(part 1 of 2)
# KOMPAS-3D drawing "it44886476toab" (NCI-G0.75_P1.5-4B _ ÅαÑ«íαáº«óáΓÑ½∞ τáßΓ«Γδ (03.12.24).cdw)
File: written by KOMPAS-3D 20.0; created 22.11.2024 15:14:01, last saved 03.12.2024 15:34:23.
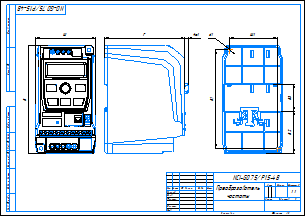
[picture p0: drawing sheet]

Sheet 1: A3, landscape

Document properties: Полное имя файла: P:\INSTART\Технический отдел\ОР\Прочие задачи\КД на номенклатурный ряд\КД на типоразмеры ПЧ\NCI\NCI-G0.75_P1.5-4B\NCI-G0.75_P1.5-4B _ Преобразователь частоты (03.12.24).cdw; Автор: admin

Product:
- Part/product: it44886476toab
    Масса: 2.32322
  - Body: Тело 2
      Масса: 0.00113358
  - Body: Тело 3
      Масса: 0.00113358
  - Body: Тело 4
      Масса: 0.000355433
  - Body: Тело 6
      Масса: 0.000355433
  - Body: Тело 7
      Масса: 0.000703761
  - Body: Тело 8
      Масса: 0.000703761
  - Body: Тело 10
      Масса: 0.0160396
  - Body: Тело 11
      Масса: 0.000703761
  - Body: Тело 13
      Масса: 0.000703761
  - Body: Тело 14
      Масса: 0.000703761
  - Body: Тело 18
      Масса: 0.0117014
  - Body: Тело 20
      Масса: 0.120334
  - Body: Тело 21
      Масса: 0.0864411
  - Body: Тело 22
      Масса: 0.0636504
  - Body: Тело 25
      Масса: 0.00135688
  - Body: Тело 26
      Масса: 0.00135688
  - Body: Тело 27
      Масса: 0.00135688
  - Body: Тело 30
      Масса: 0.000935996
  - Body: Тело 34
      Масса: 0.00831628
  - Body: Тело 36
      Масса: 0.0668131
  - Body: Тело 37
      Масса: 0.0343584
  - Body: Тело 39
      Масса: 0.0119524
  - Body: Тело 40
      Масса: 0.0119524
  - Body: Тело 42
      Масса: 0.0119524
  - Body: Тело 43
      Масса: 0.0119524
  - Body: Тело 46
      Масса: 0.0119034
  - Body: Тело 47
      Масса: 0.551587
  - Body: Тело 51
      Масса: 1.32696e-05
  - Body: Тело 54
      Масса: 1.32696e-05
  - Body: Тело 55
      Масса: 1.32696e-05
  - Body: Тело 56
      Масса: 1.32696e-05
  - Body: Тело 58
      Масса: 1.32696e-05
  - Body: Тело 61
      Масса: 1.32696e-05
  - Body: Тело 57
      Масса: 1.32696e-05
  - Body: Тело 63
      Масса: 1.65581e-05
  - Body: Тело 66
      Масса: 1.65581e-05
  - Body: Тело 67
      Масса: 1.65581e-05
  - Body: Тело 68
      Масса: 1.65581e-05
  - Body: Тело 69
      Масса: 1.65581e-05
  - Body: Тело 73
      Масса: 1.65581e-05
  - Body: Тело 48
      Масса: 0.00853877
  - Body: Тело 74
      Масса: 1.65581e-05
  - Body: Тело 78
      Масса: 1.65581e-05
  - Body: Тело 79
      Масса: 1.32696e-05
  - Body: Тело 80
      Масса: 1.32696e-05
  - Body: Тело 82
      Масса: 1.32696e-05
  - Body: Тело 83
      Масса: 1.32696e-05
  - Body: Тело 84
      Масса: 1.32696e-05
  - Body: Тело 87
      Масса: 0.000966482
  - Body: Тело 88
      Масса: 0.000873873
  - Body: Тело 15
      Масса: 0.000703761
  - Body: Тело 91
      Масса: 0.0246688
  - Body: Тело 92
      Масса: 3.83377e-05
  - Body: Тело 94
      Масса: 0.00554276
  - Body: Тело 96
      Масса: 0.00181049
  - Body: Тело 101
      Масса: 1.32696e-05
  - Body: Тело 90
      Масса: 0.000966482
  - Body: Тело 102
      Масса: 1.32696e-05
  - Body: Тело 104
      Масса: 1.32696e-05
  - Body: Тело 107
      Масса: 1.32696e-05
  - Body: Тело 108
      Масса: 1.32696e-05
  - Body: Тело 111
      Масса: 0.000194606
  - Body: Тело 115
      Масса: 0.000413213
  - Body: Тело 123
      Масса: 1.65581e-05
  - Body: Тело 127
      Масса: 1.32696e-05
  - Body: Тело 128
      Масса: 1.32696e-05
  - Body: Тело 129
      Масса: 1.32696e-05
  - Body: Тело 112
      Масса: 0.000413213
  - Body: Тело 130
      Масса: 1.32696e-05
  - Body: Тело 16
      Масса: 0.000703761
  - Body: Тело 131
      Масса: 1.32696e-05
  - Body: Тело 132
      Масса: 1.32696e-05
  - Body: Тело 133
      Масса: 1.32696e-05
  - Body: Тело 38
      Масса: 0.00631989
  - Body: Тело 135
      Масса: 1.32696e-05
  - Body: Тело 136
      Масса: 1.32696e-05
  - Body: Тело 142
      Масса: 0.000213463
  - Body: Тело 144
      Масса: 1.32696e-05
  - Body: Тело 62
      Масса: 1.32696e-05
  - Body: Тело 24
      Масса: 0.0110484
  - Body: Тело 147
      Масса: 1.32696e-05
  - Body: Тело 148
      Масса: 1.32696e-05
  - Body: Тело 154
      Масса: 1.32696e-05
  - Body: Тело 156
      Масса: 1.32696e-05
  - Body: Тело 158
      Масса: 1.32696e-05
  - Body: Тело 116
      Масса: 0.000413213
  - Body: Тело 159
      Масса: 1.32696e-05
  - Body: Тело 165
      Масса: 1.65581e-05
  - Body: Тело 166
      Масса: 1.32696e-05
  - Body: Тело 140
      Масса: 0.000213463
  - Body: Тело 169
      Масса: 1.32696e-05
  - Body: Тело 171
      Масса: 1.32696e-05
  - Body: Тело 153
      Масса: 1.32696e-05
  - Body: Тело 172
      Масса: 1.65581e-05
  - Body: Тело 173
      Масса: 1.32696e-05
  - Body: Тело 137
      Масса: 1.32696e-05
  - Body: Тело 45
      Масса: 0.0267013
  - Body: Тело 175
      Масса: 1.32696e-05
  - Body: Тело 177
      Масса: 1.32696e-05
  - Body: Тело 50
      Масса: 0.00101975
  - Body: Тело 44
      Масса: 0.0119524
  - Body: Тело 178
      Масса: 1.32696e-05
  - Body: Тело 179
      Масса: 1.32696e-05
  - Body: Тело 181
      Масса: 1.32696e-05
  - Body: Тело 182
      Масса: 1.32696e-05
  - Body: Тело 183
      Масса: 1.32696e-05
  - Body: Тело 188
      Масса: 1.32696e-05
  - Body: Тело 189
      Масса: 1.32696e-05
  - Body: Тело 192
      Масса: 1.32696e-05
  - Body: Тело 195
      Масса: 1.32696e-05
  - Body: Тело 197
      Масса: 1.32696e-05
  - Body: Тело 198
      Масса: 1.32696e-05
  - Body: Тело 199
      Масса: 1.32696e-05
  - Body: Тело 29
      Масса: 0.00135688
  - Body: Тело 201
      Масса: 1.32696e-05
  - Body: Тело 202
      Масса: 1.32696e-05
  - Body: Тело 205
      Масса: 1.32696e-05
  - Body: Тело 208
      Масса: 1.7366e-05
  - Body: Тело 209
      Масса: 1.32696e-05
  - Body: Тело 211
      Масса: 1.32696e-05
  - Body: Тело 212
      Масса: 1.32696e-05
  - Body: Тело 214
      Масса: 1.32696e-05
  - Body: Тело 9
      Масса: 0.000703761
  - Body: Тело 215
      Масса: 1.65581e-05
  - Body: Тело 217
      Масса: 1.32696e-05
  - Body: Тело 218
      Масса: 1.32696e-05
  - Body: Тело 219
      Масса: 1.32696e-05
  - Body: Тело 220
      Масса: 1.32696e-05
  - Body: Тело 221
      Масса: 1.65581e-05
  - Body: Тело 223
      Масса: 1.32696e-05
  - Body: Тело 162
      Масса: 1.65581e-05
  - Body: Тело 224
      Масса: 1.32696e-05
  - Body: Тело 228
      Масса: 1.32696e-05
  - Body: Тело 184
      Масса: 1.32696e-05
  - Body: Тело 230
      Масса: 1.32696e-05
  - Body: Тело 231
      Масса: 0.00398049
  - Body: Тело 232
      Масса: 5.48304e-05
  - Body: Тело 233
      Масса: 1.7366e-05
  - Body: Тело 1
      Масса: 0.00113358
  - Body: Тело 237
      Масса: 1.7366e-05
  - Body: Тело 141
      Масса: 0.000213463
  - Body: Тело 241
      Масса: 0.000424983
  - Body: Тело 65
      Масса: 1.65581e-05
  - Body: Тело 242
      Масса: 1.65581e-05
  - Body: Тело 243
      Масса: 1.65581e-05
  - Body: Тело 245
      Масса: 1.65581e-05
  - Body: Тело 234
      Масса: 1.7366e-05
  - Body: Тело 114
      Масса: 0.000413213
  - Body: Тело 19
      Масса: 0.0117014
  - Body: Тело 248
      Масса: 1.7366e-05
  - Body: Тело 249
      Масса: 1.7366e-05
  - Body: Тело 250
      Масса: 1.7366e-05
  - Body: Тело 254
      Масса: 1.32696e-05
  - Body: Тело 255
      Масса: 1.7366e-05
  - Body: Тело 119
      Масса: 0.000413213
  - Body: Тело 256
      Масса: 1.7366e-05
  - Body: Тело 167
      Масса: 1.32696e-05
  - Body: Тело 260
      Масса: 1.7366e-05
  - Body: Тело 261
      Масса: 3.83377e-05
  - Body: Тело 170
      Масса: 1.32696e-05
  - Body: Тело 463
      Масса: 0.000404362
  - Body: Тело 226
      Масса: 0.000413213
  - Body: Тело 464
      Масса: 0.00829425
  - Body: Тело 268
      Масса: 5.48304e-05
  - Body: Тело 467
      Масса: 0.00436982
  - Body: Тело 475
      Масса: 1.51773e-05
  - Body: Тело 451
      Масса: 6.34685e-05
  - Body: Тело 478
      Масса: 1.51773e-05
  - Body: Тело 465
      Масса: 0.00829114
  - Body: Тело 383
      Масса: 0.000340816
  - Body: Тело 125
      Масса: 1.65581e-05
  - Body: Тело 643
      Масса: 0.000158536
  - Body: Тело 514
      Масса: 1.51773e-05
  - Body: Тело 483
      Масса: 1.51773e-05
  - Body: Тело 486
      Масса: 0.000158536
  - Body: Тело 581
      Масса: 1.65581e-05
  - Body: Тело 490
      Масса: 1.51773e-05
  - Body: Тело 491
      Масса: 1.65581e-05
  - Body: Тело 433
      Масса: 0.000118347
  - Body: Тело 496
      Масса: 1.51773e-05
  - Body: Тело 437
      Масса: 0.00113358
  - Body: Тело 535
      Масса: 1.52051e-05
  - Body: Тело 498
      Масса: 1.51773e-05
  - Body: Тело 60
      Масса: 1.32696e-05
  - Body: Тело 369
      Масса: 1.32696e-05
  - Body: Тело 501
      Масса: 1.51773e-05
  - Body: Тело 503
      Масса: 1.51773e-05
  - Body: Тело 447
      Масса: 0.000307437
  - Body: Тело 187
      Масса: 1.32696e-05
  - Body: Тело 12
      Масса: 0.000703761
  - Body: Тело 507
      Масса: 1.51773e-05
  - Body: Тело 174
      Масса: 1.65581e-05
  - Body: Тело 587
      Масса: 1.32696e-05
  - Body: Тело 155
      Масса: 1.32696e-05
  - Body: Тело 512
      Масса: 1.51773e-05
  - Body: Тело 515
      Масса: 0.00507372
  - Body: Тело 510
      Масса: 1.51773e-05
  - Body: Тело 487
      Масса: 1.65581e-05
  - Body: Тело 432
      Масса: 0.000118347
  - Body: Тело 524
      Масса: 1.65581e-05
  - Body: Тело 637
      Масса: 1.51773e-05
  - Body: Тело 519
      Масса: 1.7366e-05
  - Body: Тело 427
      Масса: 1.32696e-05
  - Body: Тело 520
      Масса: 5.48304e-05
  - Body: Тело 326
      Масса: 1.32696e-05
  - Body: Тело 509
      Масса: 1.51773e-05
  - Body: Тело 571
      Масса: 0.00166679
  - Body: Тело 521
      Масса: 1.32696e-05
  - Body: Тело 522
      Масса: 1.65581e-05
  - Body: Тело 49
      Масса: 0.00944
  - Body: Тело 319
      Масса: 1.32696e-05
  - Body: Тело 458
      Масса: 1.51773e-05
  - Body: Тело 523
      Масса: 0.000255388
  - Body: Тело 191
      Масса: 1.32696e-05
  - Body: Тело 590
      Масса: 1.32696e-05
  - Body: Тело 599
      Масса: 7.12116e-06
  - Body: Тело 528
      Масса: 0.000141095
  - Body: Тело 64
      Масса: 1.65581e-05
  - Body: Тело 468
      Масса: 0.0253857
  - Body: Тело 216
      Масса: 0.000280294
  - Body: Тело 443
      Масса: 0.00113358
  - Body: Тело 239
      Масса: 5.48304e-05
  - Body: Тело 200
      Масса: 1.32696e-05
  - Body: Тело 579
      Масса: 0.00017125
  - Body: Тело 529
      Масса: 5.61948e-05
  - Body: Тело 493
      Масса: 1.51773e-05
  - Body: Тело 532
      Масса: 5.61948e-05
  - Body: Тело 343
      Масса: 0.00166679
  - Body: Тело 616
      Масса: 1.63919e-05
  - Body: Тело 462
      Масса: 0.000404362
  - Body: Тело 542
      Масса: 0.000158536
  - Body: Тело 543
      Масса: 0.000158536
  - Body: Тело 615
      Масса: 1.63919e-05
  - Body: Тело 149
      Масса: 1.32696e-05
  - Body: Тело 146
      Масса: 1.32696e-05
  - Body: Тело 469
      Масса: 0.0113891
  - Body: Тело 544
      Масса: 0.000158536
  - Body: Тело 295
      Масса: 1.65581e-05
  - Body: Тело 120
      Масса: 0.000413213
  - Body: Тело 352
      Масса: 2.90876e-05
  - Body: Тело 502
      Масса: 1.51773e-05
  - Body: Тело 461
      Масса: 0.000404362
  - Body: Тело 145
      Масса: 1.32696e-05
  - Body: Тело 545
      Масса: 1.51773e-05
  - Body: Тело 506
      Масса: 1.51773e-05
  - Body: Тело 71
      Масса: 1.65581e-05
  - Body: Тело 41
      Масса: 0.0119524
  - Body: Тело 547
      Масса: 0.000255388
  - Body: Тело 614
      Масса: 1.63919e-05
  - Body: Тело 257
      Масса: 1.7366e-05
  - Body: Тело 549
      Масса: 0.000255388
  - Body: Тело 204
      Масса: 1.32696e-05
  - Body: Тело 35
      Масса: 0.262997
  - Body: Тело 421
      Масса: 1.7366e-05
  - Body: Тело 258
      Масса: 1.7366e-05
  - Body: Тело 504
      Масса: 1.51773e-05
  - Body: Тело 366
      Масса: 1.7366e-05
  - Body: Тело 592
      Масса: 7.12116e-06
  - Body: Тело 32
      Масса: 0.0135217
  - Body: Тело 550
      Масса: 0.000255388
  - Body: Тело 157
      Масса: 1.32696e-05
  - Body: Тело 126
      Масса: 0.000512664
  - Body: Тело 314
      Масса: 1.7366e-05
  - Body: Тело 247
      Масса: 1.7366e-05
  - Body: Тело 23
      Масса: 0.0243258
  - Body: Тело 595
      Масса: 1.32696e-05
  - Body: Тело 534
      Масса: 1.32696e-05
  - Body: Тело 552
      Масса: 4.06595e-05
  - Body: Тело 176
      Масса: 1.32696e-05
  - Body: Тело 553
      Масса: 4.06595e-05
  - Body: Тело 28
      Масса: 0.00135688
  - Body: Тело 330
      Масса: 1.7366e-05
  - Body: Тело 190
      Масса: 1.32696e-05
  - Body: Тело 416
      Масса: 1.7366e-05
  - Body: Тело 435
      Масса: 0.00113358
  - Body: Тело 634
      Масса: 1.51773e-05
  - Body: Тело 555
      Масса: 0.00166679
  - Body: Тело 556
      Масса: 0.00166679
  - Body: Тело 602
      Масса: 5.61948e-05
  - Body: Тело 630
      Масса: 1.51773e-05
  - Body: Тело 558
      Масса: 0.00726683
  - Body: Тело 505
      Масса: 1.51773e-05
  - Body: Тело 500
      Масса: 1.51773e-05
  - Body: Тело 72
      Масса: 1.65581e-05
  - Body: Тело 279
      Масса: 1.32696e-05
  - Body: Тело 298
      Масса: 3.64495e-05
  - Body: Тело 168
      Масса: 1.32696e-05
  - Body: Тело 495
      Масса: 1.51773e-05
  - Body: Тело 336
      Масса: 3.64028e-05
  - Body: Тело 629
      Масса: 1.51773e-05
  - Body: Тело 263
      Масса: 1.7366e-05
  - Body: Тело 610
      Масса: 0.00166679
  - Body: Тело 609
      Масса: 1.7366e-05
  - Body: Тело 596
      Масса: 1.32696e-05
  - Body: Тело 538
      Масса: 1.51773e-05
  - Body: Тело 476
      Масса: 1.51773e-05
  - Body: Тело 227
      Масса: 1.32696e-05
  - Body: Тело 382
      Масса: 5.48304e-05
  - Body: Тело 470
      Масса: 0.00329329
  - Body: Тело 341
      Масса: 0.00166679
  - Body: Тело 426
      Масса: 1.32696e-05
  - Body: Тело 513
      Масса: 1.51773e-05
  - Body: Тело 236
      Масса: 1.7366e-05
  - Body: Тело 585
      Масса: 4.06595e-05
  - Body: Тело 649
      Масса: 0.00426189
  - Body: Тело 531
      Масса: 5.61948e-05
  - Body: Тело 627
      Масса: 0.000255388
  - Body: Тело 621
      Масса: 1.32696e-05
  - Body: Тело 349
      Масса: 1.7366e-05
  - Body: Тело 580
      Масса: 1.32696e-05
  - Body: Тело 631
      Масса: 1.51773e-05
  - Body: Тело 185
      Масса: 1.32696e-05
  - Body: Тело 117
      Масса: 0.000413213
  - Body: Тело 623
      Масса: 1.32696e-05
  - Body: Тело 605
      Масса: 5.61948e-05
  - Body: Тело 400
      Масса: 1.7366e-05
  - Body: Тело 139
      Масса: 0.000194606
  - Body: Тело 492
      Масса: 1.51773e-05
  - Body: Тело 612
      Масса: 0.000158536
  - Body: Тело 403
      Масса: 1.7366e-05
  - Body: Тело 460
      Масса: 3.90329e-05
  - Body: Тело 608
      Масса: 0.00166679
  - Body: Тело 635
      Масса: 1.65581e-05
  - Body: Тело 264
      Масса: 1.7366e-05
  - Body: Тело 646
      Масса: 0.000137594
  - Body: Тело 110
      Масса: 1.32696e-05
  - Body: Тело 302
      Масса: 1.65581e-05
  - Body: Тело 151
      Масса: 1.65581e-05
  - Body: Тело 497
      Масса: 1.51773e-05
  - Body: Тело 620
      Масса: 1.7366e-05
  - Body: Тело 518
      Масса: 0.00166679
  - Body: Тело 633
      Масса: 1.51773e-05
  - Body: Тело 564
      Масса: 4.06595e-05
  - Body: Тело 641
      Масса: 3.90329e-05
  - Body: Тело 494
      Масса: 1.51773e-05
  - Body: Тело 280
      Масса: 1.32696e-05
  - Body: Тело 81
      Масса: 1.32696e-05
  - Body: Тело 482
      Масса: 1.51773e-05
  - Body: Тело 594
      Масса: 1.32696e-05
  - Body: Тело 561
      Масса: 1.65581e-05
  - Body: Тело 253
      Масса: 1.7366e-05
  - Body: Тело 164
      Масса: 1.32696e-05
  - Body: Тело 525
      Масса: 0.000213463
  - Body: Тело 618
      Масса: 1.63919e-05
  - Body: Тело 642
      Масса: 3.90329e-05
  - Body: Тело 113
      Масса: 0.000413213
  - Body: Тело 546
      Масса: 0.000255388
  - Body: Тело 225
      Масса: 1.32696e-05
  - Body: Тело 138
      Масса: 2.23009e-05
  - Body: Тело 284
      Масса: 1.7366e-05
  - Body: Тело 485
      Масса: 0.000158536
  - Body: Тело 456
      Масса: 1.51773e-05
  - Body: Тело 489
      Масса: 1.51773e-05
  - Body: Тело 638
      Масса: 1.7366e-05
  - Body: Тело 563
      Масса: 4.06595e-05
  - Body: Тело 566
      Масса: 1.32696e-05
  - Body: Тело 160
      Масса: 1.32696e-05
  - Body: Тело 511
      Масса: 1.51773e-05
  - Body: Тело 541
      Масса: 0.000158536
  - Body: Тело 306
      Масса: 1.65581e-05
  - Body: Тело 356
      Масса: 1.65581e-05
  - Body: Тело 591
      Масса: 7.12116e-06
  - Body: Тело 313
      Масса: 1.7366e-05
  - Body: Тело 471
      Масса: 0.00329327
  - Body: Тело 289
      Масса: 1.7366e-05
  - Body: Тело 607
      Масса: 1.32696e-05
  - Body: Тело 603
      Масса: 5.61948e-05
  - Body: Тело 600
      Масса: 5.61948e-05
  - Body: Тело 121
      Масса: 0.000413213
  - Body: Тело 624
      Масса: 1.32696e-05
  - Body: Тело 527
      Масса: 0.000141095
  - Body: Тело 622
      Масса: 1.32696e-05
  - Body: Тело 484
      Масса: 0.000158536
  - Body: Тело 601
      Масса: 5.61948e-05
  - Body: Тело 296
      Масса: 3.6965e-05
  - Body: Тело 540
      Масса: 1.51773e-05
  - Body: Тело 210
      Масса: 1.32696e-05
  - Body: Тело 611
      Масса: 0.000158536
  - Body: Тело 161
      Масса: 1.32696e-05
  - Body: Тело 650
      Масса: 0.00426189
  - Body: Тело 604
      Масса: 5.61948e-05
  - Body: Тело 342
      Масса: 0.00166679
  - Body: Тело 251
      Масса: 1.7366e-05
  - Body: Тело 194
      Масса: 1.32696e-05
  - Body: Тело 568
      Масса: 1.32696e-05
  - Body: Тело 150
      Масса: 1.32696e-05
  - Body: Тело 640
      Масса: 1.63919e-05
  - Body: Тело 440
      Масса: 0.000355433
  - Body: Тело 499
      Масса: 1.51773e-05
  - Body: Тело 589
      Масса: 1.32696e-05
  - Body: Тело 361
      Масса: 1.32696e-05
  - Body: Тело 619
      Масса: 1.32696e-05
  - Body: Тело 405
      Масса: 1.32696e-05
  - Body: Тело 551
      Масса: 0.000255388
  - Body: Тело 598
      Масса: 7.12116e-06
  - Body: Тело 583
      Масса: 4.06595e-05
  - Body: Тело 411
      Масса: 5.48304e-05
  - Body: Тело 367
      Масса: 1.32696e-05
  - Body: Тело 488
      Масса: 1.51773e-05
  - Body: Тело 163
      Масса: 1.32696e-05
  - Body: Тело 109
      Масса: 1.32696e-05
  - Body: Тело 408
      Масса: 5.48304e-05
  - Body: Тело 593
      Масса: 1.32696e-05
  - Body: Тело 387
      Масса: 1.32696e-05
  - Body: Тело 613
      Масса: 1.63919e-05
  - Body: Тело 597
      Масса: 7.12116e-06
  - Body: Тело 118
      Масса: 0.000413213
  - Body: Тело 565
      Масса: 4.06595e-05
  - Body: Тело 632
      Масса: 1.51773e-05
  - Body: Тело 379
      Масса: 1.32696e-05
  - Body: Тело 562
      Масса: 0.000382752
  - Body: Тело 262
      Масса: 1.7366e-05
  - Body: Тело 586
      Масса: 1.32696e-05
  - Body: Тело 647
      Масса: 0.00426189
  - Body: Тело 533
      Масса: 5.61948e-05
  - Body: Тело 472
      Масса: 0.00329327
  - Body: Тело 409
      Масса: 5.48304e-05
  - Body: Тело 548
      Масса: 2.98222e-05
  - Body: Тело 474
      Масса: 1.51773e-05
  - Body: Тело 363
      Масса: 1.32696e-05
  - Body: Тело 276
      Масса: 1.7366e-05
  - Body: Тело 588
      Масса: 1.32696e-05
  - Body: Тело 70
      Масса: 1.65581e-05
  - Body: Тело 584
      Масса: 4.06595e-05
  - Body: Тело 644
      Масса: 0.000158536
  - Body: Тело 625
      Масса: 1.32696e-05
  - Body: Тело 213
      Масса: 1.32696e-05
  - Body: Тело 275
      Масса: 1.7366e-05
  - Body: Тело 320
      Масса: 1.32696e-05
  - Body: Тело 399
      Масса: 1.32696e-05
  - Body: Тело 574
      Масса: 4.06595e-05
  - Body: Тело 85
      Масса: 1.32696e-05
  - Body: Тело 576
      Масса: 1.32696e-05
  - Body: Тело 575
      Масса: 1.32696e-05
  - Body: Тело 376
      Масса: 1.32696e-05
  - Body: Тело 316
      Масса: 1.32696e-05
  - Body: Тело 449
      Масса: 0.0658364
  - Body: Тело 152
      Масса: 1.32696e-05
  - Body: Тело 559
      Масса: 1.65581e-05
  - Body: Тело 645
      Масса: 1.32696e-05
  - Body: Тело 207
      Масса: 1.32696e-05
  - Body: Тело 567
      Масса: 1.32696e-05
  - Body: Тело 572
      Масса: 1.32696e-05
  - Body: Тело 203
      Масса: 1.32696e-05
  - Body: Тело 582
      Масса: 1.65581e-05
  - Body: Тело 134
      Масса: 1.32696e-05
  - Body: Тело 626
      Масса: 1.32696e-05
  - Body: Тело 578
      Масса: 1.32696e-05
  - Body: Тело 569
      Масса: 1.32696e-05
  - Body: Тело 557
      Масса: 0.00166679
  - Body: Тело 459
      Масса: 3.90329e-05
  - Body: Тело 457
      Масса: 1.51773e-05
  - Body: Тело 539
      Масса: 1.51773e-05
  - Body: Тело 455
      Масса: 1.51773e-05
  - Body: Тело 428
      Масса: 0.146258
  - Body: Тело 454
      Масса: 0.000382752
  - Body: Тело 453
      Масса: 1.63919e-05
  - Body: Тело 417
      Масса: 1.32696e-05
  - Body: Тело 517
      Масса: 0.00106884
  - Body: Тело 418
      Масса: 1.7366e-05
  - Body: Тело 401
      Масса: 1.32696e-05
  - Body: Тело 53
      Масса: 1.32696e-05
  - Body: Тело 452
      Масса: 1.63919e-05
  - Body: Тело 315
      Масса: 1.7366e-05
  - Body: Тело 222
      Масса: 1.32696e-05
  - Body: Тело 450
      Масса: 6.34685e-05
  - Body: Тело 481
      Масса: 1.51773e-05
  - Body: Тело 448
      Масса: 0.000307437
  - Body: Тело 193
      Масса: 1.32696e-05
  - Body: Тело 392
      Масса: 1.32696e-05
  - Body: Тело 577
      Масса: 1.7366e-05
  - Body: Тело 508
      Масса: 1.51773e-05
  - Body: Тело 106
      Масса: 1.32696e-05
  - Body: Тело 438
      Масса: 0.000355433
  - Body: Тело 445
      Масса: 0.00113358
  - Body: Тело 246
      Масса: 1.65581e-05
  - Body: Тело 444
      Масса: 0.000355433
  - Body: Тело 554
      Масса: 4.06595e-05
  - Body: Тело 442
      Масса: 0.000355433
  - Body: Тело 441
      Масса: 0.00113358
  - Body: Тело 323
      Масса: 1.32696e-05
  - Body: Тело 606
      Масса: 0.000137594
  - Body: Тело 439
      Масса: 0.00113358
  - Body: Тело 436
      Масса: 0.000355433
  - Body: Тело 344
      Масса: 1.32696e-05
  - Body: Тело 124
      Масса: 1.65581e-05
  - Body: Тело 5
      Масса: 0.000355433
  - Body: Тело 434
      Масса: 0.000355433
  - Body: Тело 329
      Масса: 1.32696e-05
  - Body: Тело 364
      Масса: 1.32696e-05
  - Body: Тело 431
      Масса: 0.146258
  - Body: Тело 345
      Масса: 1.32696e-05
  - Body: Тело 350
      Масса: 1.7366e-05
  - Body: Тело 430
      Масса: 0.146258
  - Body: Тело 334
      Масса: 1.7366e-05
  - Body: Тело 429
      Масса: 0.146258
  - Body: Тело 206
      Масса: 1.32696e-05
  - Body: Тело 271
      Масса: 1.32696e-05
  - Body: Тело 365
      Масса: 1.32696e-05
  - Body: Тело 425
      Масса: 1.32696e-05
  - Body: Тело 305
      Масса: 1.65581e-05
  - Body: Тело 98
      Масса: 1.65581e-05
  - Body: Тело 424
      Масса: 1.7366e-05
  - Body: Тело 423
      Масса: 1.32696e-05
  - Body: Тело 381
      Масса: 1.7366e-05
  - Body: Тело 422
      Масса: 5.48304e-05
  - Body: Тело 186
      Масса: 1.32696e-05
  - Body: Тело 420
      Масса: 1.7366e-05
  - Body: Тело 648
      Масса: 0.00426189
  - Body: Тело 419
      Масса: 1.32696e-05
  - Body: Тело 235
      Масса: 1.7366e-05
  - Body: Тело 415
      Масса: 1.7366e-05
  - Body: Тело 537
      Масса: 0.000158536
  - Body: Тело 414
      Масса: 1.32696e-05
  - Body: Тело 413
      Масса: 1.32696e-05
  - Body: Тело 412
      Масса: 1.7366e-05
  - Body: Тело 636
      Масса: 1.65581e-05
  - Body: Тело 410
      Масса: 5.48304e-05
  - Body: Тело 97
      Масса: 0.0015961
  - Body: Тело 407
      Масса: 5.48304e-05
  - Body: Тело 52
      Масса: 1.32696e-05
  - Body: Тело 393
      Масса: 1.32696e-05
  - Body: Тело 406
      Масса: 1.65581e-05
  - Body: Тело 89
      Масса: 0.00142218
  - Body: Тело 404
      Масса: 1.32696e-05
  - Body: Тело 339
      Масса: 1.32696e-05
  - Body: Тело 59
      Масса: 1.32696e-05
  - Body: Тело 402
      Масса: 1.7366e-05
  - Body: Тело 479
      Масса: 1.51773e-05
  - Body: Тело 398
      Масса: 1.65581e-05
  - Body: Тело 397
      Масса: 1.32696e-05
  - Body: Тело 396
      Масса: 1.7366e-05
  - Body: Тело 354
      Масса: 0.000213463
  - Body: Тело 395
      Масса: 1.32696e-05
  - Body: Тело 394
      Масса: 1.32696e-05
  - Body: Тело 143
      Масса: 1.32696e-05
  - Body: Тело 390
      Масса: 1.65581e-05
  - Body: Тело 93
      Масса: 3.83377e-05
  - Body: Тело 389
      Масса: 1.65581e-05
  - Body: Тело 388
      Масса: 1.32696e-05
  - Body: Тело 229
      Масса: 1.32696e-05
  - Body: Тело 386
      Масса: 1.32696e-05
  - Body: Тело 291
      Масса: 0.000213463
  - Body: Тело 385
      Масса: 1.32696e-05
  - Body: Тело 639
      Масса: 1.63919e-05
  - Body: Тело 380
      Масса: 1.32696e-05
  - Body: Тело 322
      Масса: 1.32696e-05
  - Body: Тело 372
      Масса: 1.7366e-05
  - Body: Тело 95
      Масса: 0.000935996
  - Body: Тело 378
      Масса: 0.000413213
  - Body: Тело 259
      Масса: 1.7366e-05
  - Body: Тело 76
      Масса: 1.65581e-05
  - Body: Тело 351
      Масса: 2.90876e-05
  - Body: Тело 375
      Масса: 1.32696e-05
  - Body: Тело 373
      Масса: 1.32696e-05
  - Body: Тело 75
      Масса: 1.32696e-05
  - Body: Тело 371
      Масса: 1.7366e-05
  - Body: Тело 628
      Масса: 1.51773e-05
  - Body: Тело 333
      Масса: 1.32696e-05
  - Body: Тело 370
      Масса: 1.32696e-05
  - Body: Тело 368
      Масса: 1.32696e-05
  - Body: Тело 310
      Масса: 1.7366e-05
  - Body: Тело 86
      Масса: 1.32696e-05
  - Body: Тело 286
      Масса: 1.7366e-05
  - Body: Тело 359
      Масса: 1.7366e-05
  - Body: Тело 358
      Масса: 5.48304e-05
  - Body: Тело 466
      Масса: 0.00829114
  - Body: Тело 355
      Масса: 5.48304e-05
  - Body: Тело 353
      Масса: 1.7366e-05
  - Body: Тело 362
      Масса: 1.32696e-05
  - Body: Тело 281
      Масса: 1.32696e-05
  - Body: Тело 335
      Масса: 1.32696e-05
  - Body: Тело 346
      Масса: 1.32696e-05
  - Body: Тело 357
      Масса: 1.65581e-05
  - Body: Тело 196
      Масса: 1.32696e-05
  - Body: Тело 340
      Масса: 1.32696e-05
  - Body: Тело 570
      Масса: 4.06595e-05
  - Body: Тело 338
      Масса: 1.7366e-05
  - Body: Тело 337
      Масса: 1.7366e-05
  - Body: Тело 446
      Масса: 0.000307437
  - Body: Тело 332
      Масса: 1.7366e-05
  - Body: Тело 331
      Масса: 1.7366e-05
  - Body: Тело 301
      Масса: 1.65581e-05
  - Body: Тело 328
      Масса: 1.7366e-05
  - Body: Тело 105
      Масса: 1.32696e-05
  - Body: Тело 100
      Масса: 1.65581e-05
  - Body: Тело 31
      Масса: 0.0078835
  - Body: Тело 327
      Масса: 1.32696e-05
  - Body: Тело 617
      Масса: 1.63919e-05
  - Body: Тело 99
      Масса: 1.65581e-05
  - Body: Тело 325
      Масса: 1.32696e-05
  - Body: Тело 293
      Масса: 5.48304e-05
  - Body: Тело 288
      Масса: 1.7366e-05
  - Body: Тело 480
      Масса: 1.51773e-05
  - Body: Тело 324
      Масса: 1.32696e-05
  - Body: Тело 321
      Масса: 1.32696e-05
  - Body: Тело 318
      Масса: 1.32696e-05
  - Body: Тело 317
      Масса: 1.32696e-05
  - Body: Тело 312
      Масса: 5.48304e-05
  - Body: Тело 560
      Масса: 1.65581e-05
  - Body: Тело 122
      Масса: 1.65581e-05
  - Body: Тело 311
      Масса: 5.48304e-05
  - Body: Тело 473
      Масса: 0.00425494
  - Body: Тело 309
      Масса: 1.32696e-05
  - Body: Тело 240
      Масса: 1.7366e-05
  - Body: Тело 180
      Масса: 1.32696e-05
  - Body: Тело 308
      Масса: 0.000413213
  - Body: Тело 307
      Масса: 0.000213463
  - Body: Тело 304
      Масса: 1.65581e-05
  - Body: Тело 347
      Масса: 1.32696e-05
  - Body: Тело 360
      Масса: 1.32696e-05
  - Body: Тело 384
      Масса: 5.48304e-05
  - Body: Тело 516
      Масса: 0.00507377
  - Body: Тело 303
      Масса: 1.65581e-05
  - Body: Тело 300
      Масса: 1.65581e-05
  - Body: Тело 283
      Масса: 1.7366e-05
  - Body: Тело 299
      Масса: 3.64028e-05
  - Body: Тело 297
      Масса: 3.64631e-05
  - Body: Тело 294
      Масса: 0.000413213
  - Body: Тело 252
      Масса: 5.48304e-05
  - Body: Тело 33
      Масса: 0.00516019
  - Body: Тело 292
      Масса: 1.7366e-05
  - Body: Тело 269
      Масса: 5.48304e-05
  - Body: Тело 290
      Масса: 0.000413213
  - Body: Тело 287
      Масса: 1.32696e-05
  - Body: Тело 285
      Масса: 5.48304e-05
  - Body: Тело 391
      Масса: 1.32696e-05
  - Body: Тело 526
      Масса: 5.61948e-05
  - Body: Тело 477
      Масса: 1.51773e-05
  - Body: Тело 282
      Масса: 1.7366e-05
  - Body: Тело 278
      Масса: 1.7366e-05
  - Body: Тело 530
      Масса: 5.61948e-05
  - Body: Тело 277
      Масса: 1.7366e-05
  - Body: Тело 274
      Масса: 1.7366e-05
  - Body: Тело 238
      Масса: 1.7366e-05
  - Body: Тело 273
      Масса: 5.48304e-05
  - Body: Тело 272
      Масса: 1.7366e-05
  - Body: Тело 377
      Масса: 1.65581e-05
  - Body: Тело 536
      Масса: 0.000158536
  - Body: Тело 244
      Масса: 1.65581e-05
  - Body: Тело 77
      Масса: 1.32696e-05
  - Body: Тело 270
      Масса: 1.7366e-05
  - Body: Тело 348
      Масса: 1.32696e-05
  - Body: Тело 573
      Масса: 4.06595e-05
  - Body: Тело 103
      Масса: 1.32696e-05
  - Body: Тело 267
      Масса: 1.7366e-05
  - Body: Тело 266
      Масса: 1.7366e-05
  - Body: Тело 265
      Масса: 1.32696e-05
  - Body: Тело 374
      Масса: 5.48304e-05
  - Body: Тело 17
      Масса: 0.0117014

Title block, sheet 1: Наименование: Преобразователь / частоты; designation: NCI-G0.75/P1.5-4B; Количество листов документа: 1; Форматы листов документа: A3; stored path: P:\INSTART\Технический отдел\ОР\Прочие задачи\КД на номенклатурный ряд\КД на типоразмеры ПЧ\NCI\NCI-G0.75_P1.5-4B\NCI-G0.75_P1.5-4B _ Преобразователь частоты.cdw

Views: Вид 1
Referenced files in P:\INSTART\Технический отдел\ОР\Уралов\Проверка КД\: KD600M-4T2R2-20240807.m3d
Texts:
  Кривая без истории:10000
  Кривая без истории:10001
  Кривая без истории:10002
  Кривая без истории:10003
  Кривая без истории:10004
  Кривая без истории:10005
  Кривая без истории:10006
  Кривая без истории:10007
  Кривая без истории:10008
  Кривая без истории:10009
  Кривая без истории:10010
  Кривая без истории:10011
  Кривая без истории:10012
  Кривая без истории:10013
  Кривая без истории:10014
  Кривая без истории:10015
  Кривая без истории:10016
  Кривая без истории:10017
  Кривая без истории:10018
  Кривая без истории:10019
  Кривая без истории:10020
  Кривая без истории:10021
  Кривая без истории:10022
  Кривая без истории:10023
  Кривая без истории:10024
  Кривая без истории:10025
  Кривая без истории:10026
  Кривая без истории:10027
  Кривая без истории:10028
  Кривая без истории:10029
  Кривая без истории:10030
  Кривая без истории:10031
  Кривая без истории:10032
  Кривая без истории:10033
  Кривая без истории:10034
  Кривая без истории:10035
  Кривая без истории:10036
  Кривая без истории:10037
  Кривая без истории:10038
  Кривая без истории:10039
  Кривая без истории:10040
  Кривая без истории:10041
  Кривая без истории:10042
  Кривая без истории:10043
  Кривая без истории:10044
  Кривая без истории:10045
  Кривая без истории:10046
  Кривая без истории:10047
  Кривая без истории:10048
  Кривая без истории:10049
  Кривая без истории:10050
  Кривая без истории:10051
  Кривая без истории:10052
  Кривая без истории:10053
  Кривая без истории:10054
  Кривая без истории:10055
  Кривая без истории:10056
  Кривая без истории:10057
  Кривая без истории:10058
  Кривая без истории:10059
  Кривая без истории:10060
  Кривая без истории:10061
  Кривая без истории:10062
  Кривая без истории:10063
  Кривая без истории:10064
  Кривая без истории:10065
  Кривая без истории:10066
  Кривая без истории:10067
  Кривая без истории:10068
  Кривая без истории:10069
  Кривая без истории:10070
  Кривая без истории:10071
  Кривая без истории:10072
  Кривая без истории:10073
  Кривая без истории:10074
  Кривая без истории:10075
  Кривая без истории:10076
  Кривая без истории:10077
  Кривая без истории:10078
  Кривая без истории:10079
  Кривая без истории:10080
  Кривая без истории:10081
  Кривая без истории:10082
  Кривая без истории:10083
  Кривая без истории:10084
  Кривая без истории:10085
  Кривая без истории:10086
  Кривая без истории:10087
  Кривая без истории:10088
  Кривая без истории:10089
  Кривая без истории:10090
  Кривая без истории:10091
  Кривая без истории:10092
  Кривая без истории:10093
  Кривая без истории:10094
  Кривая без истории:10095
  Кривая без истории:10096
  Кривая без истории:10097
  Кривая без истории:10098
  Кривая без истории:10099
  Кривая без истории:10100
  Кривая без истории:10101
  Кривая без истории:10102
  Кривая без истории:10103
  Кривая без истории:10104
  Кривая без истории:10105
  Кривая без истории:10106
  Кривая без истории:10107
  Кривая без истории:10108
  Кривая без истории:10109
  Кривая без истории:10110
  Кривая без истории:10111
  Кривая без истории:10112
  Кривая без истории:10113
  Кривая без истории:10114
  Кривая без истории:10115
  Кривая без истории:10116
  Кривая без истории:10117
  Кривая без истории:10118
  Кривая без истории:10119
  Кривая без истории:10120
  Кривая без истории:10121
  Кривая без истории:10122
  Кривая без истории:10123
  Кривая без истории:10124
  Кривая без истории:10125
  Кривая без истории:10126
  Кривая без истории:10127
  Кривая без истории:10128
  Кривая без истории:10129
  Кривая без истории:10130
  Кривая без истории:10131
  Кривая без истории:10132
  Кривая без истории:10133
  Кривая без истории:10134
  Кривая без истории:10135
  Кривая без истории:10136
  Кривая без истории:10137
  Кривая без истории:10138
  Кривая без истории:10139
  Кривая без истории:10140
  Кривая без истории:10141
  Кривая без истории:10142
  Кривая без истории:10143
  Кривая без истории:10144
  Кривая без истории:10145
  Кривая без истории:10146
  Кривая без истории:10147
  Кривая без истории:10148
  Кривая без истории:10149
  Кривая без истории:10150
  Кривая без истории:10151
  Кривая без истории:10152
  Кривая без истории:10153
  Кривая без истории:10154
  Кривая без истории:10155
  Кривая без истории:10156
  Кривая без истории:10157
  Кривая без истории:10158
  Кривая без истории:10159
  Кривая без истории:10160
  Кривая без истории:10161
  Кривая без истории:10162
  Кривая без истории:10163
  Кривая без истории:10164
  Кривая без истории:10165
  Кривая без истории:10166
  Кривая без истории:10167
  Кривая без истории:10168
  Кривая без истории:10169
  Кривая без истории:10170
  Кривая без истории:10171
  Кривая без истории:10172
  Кривая без истории:10173
  Кривая без истории:10174
  Кривая без истории:10175
  Кривая без истории:10176
  Кривая без истории:10177
  Кривая без истории:10178
  Кривая без истории:10179
  Кривая без истории:10180
  Кривая без истории:10181
  Кривая без истории:10182
  Кривая без истории:10183
  Кривая без истории:10184
  Кривая без истории:10185
  Кривая без истории:10186
  Кривая без истории:10187
  Кривая без истории:10188
  Кривая без истории:10189
  Кривая без истории:10190
  Кривая без истории:10191
  Кривая без истории:10192
  Кривая без истории:10193
  Кривая без истории:10194
  Кривая без истории:10195
  Кривая без истории:10196
  Кривая без истории:10197
  Кривая без истории:10198
  Кривая без истории:10199
  Кривая без истории:10200
  Кривая без истории:10201
  Кривая без истории:10202
  Кривая без истории:10203
  Кривая без истории:10204
  Кривая без истории:10205
  Кривая без истории:10206
  Кривая без истории:10207
  Кривая без истории:10208
  Кривая без истории:10209
  Кривая без истории:10210
  Кривая без истории:10211
  Кривая без истории:10212
  Кривая без истории:10213
  Кривая без истории:10214
  Кривая без истории:10215
  Кривая без истории:10216
  Кривая без истории:10217
  Кривая без истории:10218
  Кривая без истории:10219
  Кривая без истории:10220
  Кривая без истории:10221
  Кривая без истории:10222
  Кривая без истории:10223
  Кривая без истории:10224
  Кривая без истории:10225
  Кривая без истории:10226
  Кривая без истории:10227
  Кривая без истории:10228
  Кривая без истории:10229
  Кривая без истории:10230
  Кривая без истории:10231
  Кривая без истории:10232
  Кривая без истории:10233
  Кривая без истории:10234
  Кривая без истории:10235
  Кривая без истории:10236
  Кривая без истории:10237
  Кривая без истории:10238
  Кривая без истории:10239
  Кривая без истории:10240
  Кривая без истории:10241
  Кривая без истории:10242
  Кривая без истории:10243
  Кривая без истории:10244
  Кривая без истории:10245
  Кривая без истории:10246
  Кривая без истории:10247
  Кривая без истории:10248
  Кривая без истории:10249
  Кривая без истории:10250
  Кривая без истории:10251
  Кривая без истории:10252
  Кривая без истории:10253
  Кривая без истории:10254
  Кривая без истории:10255
  Кривая без истории:10256
  Кривая без истории:10257
  Кривая без истории:10258
  Кривая без истории:10259
  Кривая без истории:10260
  Кривая без истории:10261
  Кривая без истории:10262
  Кривая без истории:10263
  Кривая без истории:10264
  Кривая без истории:10265
  Кривая без истории:10266
  Кривая без истории:10267
  Кривая без истории:10268
  Кривая без истории:10269
  Кривая без истории:10270
  Кривая без истории:10271
  Кривая без истории:10272
  Кривая без истории:10273
  Кривая без истории:10274
  Кривая без истории:10275
  Кривая без истории:10276
  Кривая без истории:10277
  Кривая без истории:10278
  Кривая без истории:10279
  Кривая без истории:10280
  Кривая без истории:10281
  Кривая без истории:10282
  Кривая без истории:10283
  Кривая без истории:10284
  Кривая без истории:10285
  Кривая без истории:10286
  Кривая без истории:10287
  Кривая без истории:10288
  Кривая без истории:10289
  Кривая без истории:10290
  Кривая без истории:10291
  Кривая без истории:10292
  Кривая без истории:10293
  Кривая без истории:10294
  Кривая без истории:10295
  Кривая без истории:10296
  Кривая без истории:10297
  Кривая без истории:10298
  Кривая без истории:10299
  Кривая без истории:10300
  Кривая без истории:10301
  Кривая без истории:10302
  Кривая без истории:10303
  Кривая без истории:10304
  Кривая без истории:10305
  Кривая без истории:10306
  Кривая без истории:10307
  Кривая без истории:10308
  Кривая без истории:10309
  Кривая без истории:10310
  Кривая без истории:10311
  Кривая без истории:10312
  Кривая без истории:10313
  Кривая без истории:10314
  Кривая без истории:10315
  Кривая без истории:10316
  Кривая без истории:10317
  Кривая без истории:10318
  Кривая без истории:10319
  Кривая без истории:10320
  Кривая без истории:10321
  Кривая без истории:10322
  Кривая без истории:10323
  Кривая без истории:10324
  Кривая без истории:10325
  Кривая без истории:10326
  Кривая без истории:10327
  Кривая без истории:10328
  Кривая без истории:10329
  Кривая без истории:10330
  Кривая без истории:10331
  Кривая без истории:10332
  Кривая без истории:10333
  Кривая без истории:10334
  Кривая без истории:10335
  Кривая без истории:10336
  Кривая без истории:10337
  Кривая без истории:10338
  Кривая без истории:10339
  Кривая без истории:10340
  Кривая без истории:10341
  Кривая без истории:10342
  Кривая без истории:10343
  Кривая без истории:10344
  Кривая без истории:10345
  Кривая без истории:10346
  Кривая без истории:10347
  Кривая без истории:10348
  Кривая без истории:10349
  Кривая без истории:10350
  Кривая без истории:10351
  Кривая без истории:10352
  Кривая без истории:10353
  Кривая без истории:10354
  Кривая без истории:10355
  Кривая без истории:10356
  Кривая без истории:10357
  Кривая без истории:10358
  Кривая без истории:10359
  Кривая без истории:10360
  Кривая без истории:10361
  Кривая без истории:10362
  Кривая без истории:10363
  Кривая без истории:10364
  Кривая без истории:10365
  Кривая без истории:10366
  Кривая без истории:10367
  Кривая без истории:10368
  Кривая без истории:10369
  Кривая без истории:10370
  Кривая без истории:10371
  Кривая без истории:10372
  Кривая без истории:10373
  Кривая без истории:10374
  Кривая без истории:10375
  Кривая без истории:10376
  Кривая без истории:10377
  Кривая без истории:10378
  Кривая без истории:10379
  Кривая без истории:10380
  Кривая без истории:10381
  Кривая без истории:10382
  Кривая без истории:10383
  Кривая без истории:10384
  Кривая без истории:10385
  Кривая без истории:10386
  Кривая без истории:10387
  Кривая без истории:10388
  Кривая без истории:10389
  Кривая без истории:10390
  Кривая без истории:10391
  Кривая без истории:10392
  Кривая без истории:10393
  Кривая без истории:10394
  Кривая без истории:10395
  Кривая без истории:10396
  Кривая без истории:10397
  Кривая без истории:10398
  Кривая без истории:10399
  Кривая без истории:10400
  Кривая без истории:10401
  Кривая без истории:10402
  Кривая без истории:10403
  Кривая без истории:10404
  Кривая без истории:10405
  Кривая без истории:10406
  Кривая без истории:10407
  Кривая без истории:10408
  Кривая без истории:10409
  Кривая без истории:10410
  Кривая без истории:10411
  Кривая без истории:10412
  Кривая без истории:10413
  Кривая без истории:10414
  Кривая без истории:10415
  Кривая без истории:10416
  Кривая без истории:10417
  Кривая без истории:10418
  Кривая без истории:10419
  Кривая без истории:10420
  Кривая без истории:10421
  Кривая без истории:10422
  Кривая без истории:10423
  Кривая без истории:10424
  Кривая без истории:10425
  Кривая без истории:10426
  Кривая без истории:10427
  Кривая без истории:10428
  Кривая без истории:10429
  Кривая без истории:10430
  Кривая без истории:10431
  Кривая без истории:10432
  Кривая без истории:10433
  Кривая без истории:10434
  Кривая без истории:10435
  Кривая без истории:10436
  Кривая без истории:10437
  Кривая без истории:10438
  Кривая без истории:10439
  Кривая без истории:10440
  Кривая без истории:10441
  Кривая без истории:10442
  Кривая без истории:10443
  Кривая без истории:10444
  Кривая без истории:10445
  Кривая без истории:10446
  Кривая без истории:10447
  Кривая без истории:10448
  Кривая без истории:10449
  Кривая без истории:10450
  Кривая без истории:10451
  Кривая без истории:10452
  Кривая без истории:10453
  Кривая без истории:10454
  Кривая без истории:10455
  Кривая без истории:10456
  Кривая без истории:10457
  Кривая без истории:10458
  Кривая без истории:10459
  Кривая без истории:10460
  Кривая без истории:10461
  Кривая без истории:10462
  Кривая без истории:10463
  Кривая без истории:10464
  Кривая без истории:10465
  Кривая без истории:10466
  Кривая без истории:10467
  Кривая без истории:10468
  Кривая без истории:10469
  Кривая без истории:10470
  Кривая без истории:10471
  Кривая без истории:10472
  Кривая без истории:10473
  Кривая без истории:10474
  Кривая без истории:10475
  Кривая без истории:10476
  Кривая без истории:10477
  Кривая без истории:10478
  Кривая без истории:10479
  Кривая без истории:10480
  Кривая без истории:10481
  Кривая без истории:10482
  Кривая без истории:10483
  Кривая без истории:10484
  Кривая без истории:10485
  Кривая без истории:10486
  Кривая без истории:10487
  Кривая без истории:10488
  Кривая без истории:10489
  Кривая без истории:10490
  Кривая без истории:10491
  Кривая без истории:10492
  Кривая без истории:10493
  Кривая без истории:10494
  Кривая без истории:10495
  Кривая без истории:10496
  Кривая без истории:10497
  Кривая без истории:10498
  Кривая без истории:10499
  Кривая без истории:10500
  Кривая без истории:10501
  Кривая без истории:10502
  Кривая без истории:10503
  Кривая без истории:10504
  Кривая без истории:10505
  Кривая без истории:10506
  Кривая без истории:10507
  Кривая без истории:10508
  Кривая без истории:10509
  Кривая без истории:10510
  Кривая без истории:10511
  Кривая без истории:10512
  Кривая без истории:10513
  Кривая без истории:10514
  Кривая без истории:10515
  Кривая без истории:10516
  Кривая без истории:10517
  Кривая без истории:10518
  Кривая без истории:10519
  Кривая без истории:10520
  Кривая без истории:10521
  Кривая без истории:10522
  Кривая без истории:10523
  Кривая без истории:10524
  Кривая без истории:10525
  Кривая без истории:10526
  Кривая без истории:10527
  Кривая без истории:10528
  Кривая без истории:10529
  Кривая без истории:10530
  Кривая без истории:10531
  Кривая без истории:10532
  Кривая без истории:10533
  Кривая без истории:10534
  Кривая без истории:10535
  Кривая без истории:10536
  Кривая без истории:10537
  Кривая без истории:10538
  Кривая без истории:10539
  Кривая без истории:10540
  Кривая без истории:10541
  Кривая без истории:10542
  Кривая без истории:10543
  Кривая без истории:10544
  Кривая без истории:10545
  Кривая без истории:10546
  Кривая без истории:10547
  Кривая без истории:10548
  Кривая без истории:10549
  Кривая без истории:10550
  Кривая без истории:10551
  Кривая без истории:10552
  Кривая без истории:10553
  Кривая без истории:10554
  Кривая без истории:10555
  Кривая без истории:10556
  Кривая без истории:10557
  Кривая без истории:10558
  Кривая без истории:10559
  Кривая без истории:10560
  Кривая без истории:10561
  Кривая без истории:10562
  Кривая без истории:10563
  Кривая без истории:10564
  Кривая без истории:10565
  Кривая без истории:10566
  Кривая без истории:10567
  Кривая без истории:10568
  Кривая без истории:10569
  Кривая без истории:10570
  Кривая без истории:10571
  Кривая без истории:10572
  Кривая без истории:10573
  Кривая без истории:10574
  Кривая без истории:10575
  Кривая без истории:10576
  Кривая без истории:10577
  Кривая без истории:10578
  Кривая без истории:10579
  Кривая без истории:10580
  Кривая без истории:10581
  Кривая без истории:10582
  Кривая без истории:10583
  Кривая без истории:10584
  Кривая без истории:10585
  Кривая без истории:10586
  Кривая без истории:10587
  Кривая без истории:10588
  Кривая без истории:10589
  Кривая без истории:10590
  Кривая без истории:10591
  Кривая без истории:10592
  Кривая без истории:10593
  Кривая без истории:10594
  Кривая без истории:10595
  Кривая без истории:10596
  Кривая без истории:10597
  Кривая без истории:10598
  Кривая без истории:10599
  Кривая без истории:10600
  Кривая без истории:10601
  Кривая без истории:10602
  Кривая без истории:10603
  Кривая без истории:10604
  Кривая без истории:10605
  Кривая без истории:10606
  Кривая без истории:10607
  Кривая без истории:10608
  Кривая без истории:10609
  Кривая без истории:10610
  Кривая без истории:10611
  Кривая без истории:10612
  Кривая без истории:10613
  Кривая без истории:10614
  Кривая без истории:10615
  Кривая без истории:10616
  Кривая без истории:10617
  Кривая без истории:10618
  Кривая без истории:10619
  Кривая без истории:10620
  Кривая без истории:10621
  Кривая без истории:10622
  Кривая без истории:10623
  Кривая без истории:10624
  Кривая без истории:10625
  Кривая без истории:10626
  Кривая без истории:10627
  Кривая без истории:10628
  Кривая без истории:10629
  Кривая без истории:10630
  Кривая без истории:10631
  Кривая без истории:10632
  Кривая без истории:10633
  Кривая без истории:10634
  Кривая без истории:10635
  Кривая без истории:10636
  Кривая без истории:10637
  Кривая без истории:10638
  Кривая без истории:10639
  Кривая без истории:10640
  Кривая без истории:10641
  Кривая без истории:10642
  Кривая без истории:10643
  Кривая без истории:10644
  Кривая без истории:10645
  Кривая без истории:10646
  Кривая без истории:10647
  Кривая без истории:10648
  Кривая без истории:10649
  Кривая без истории:10650
  Кривая без истории:10651
  Кривая без истории:10652
  Кривая без истории:10653
  Кривая без истории:10654
  Кривая без истории:10655
  Кривая без истории:10656
  Кривая без истории:10657
  Кривая без истории:10658
  Кривая без истории:10659
  Кривая без истории:10660
  Кривая без истории:10661
  Кривая без истории:10662
  Кривая без истории:10663
  Кривая без истории:10664
  Кривая без истории:10665
  Кривая без истории:10666
  Кривая без истории:10667
  Кривая без истории:10668
  Кривая без истории:10669
  Кривая без истории:10670
  Кривая без истории:10671
  Кривая без истории:10672
  Кривая без истории:10673
  Кривая без истории:10674
  Кривая без истории:10675
  Кривая без истории:10676
  Кривая без истории:10677
  Кривая без истории:10678
  Кривая без истории:10679
  Кривая без истории:10680
  Кривая без истории:10681
  Кривая без истории:10682
  Кривая без истории:10683
  Кривая без истории:10684
  Кривая без истории:10685
  Кривая без истории:10686
  Кривая без истории:10687
  Кривая без истории:10688
  Кривая без истории:10689
  Кривая без истории:10690
  Кривая без истории:10691
  Кривая без истории:10692
  Кривая без истории:10693
  Кривая без истории:10694
  Кривая без истории:10695
  Кривая без истории:10696
  Кривая без истории:10697
  Кривая без истории:10698
  Кривая без истории:10699
  Кривая без истории:10700
  Кривая без истории:10701
  Кривая без истории:10702
  Кривая без истории:10703
  Кривая без истории:10704
  Кривая без истории:10705
  Кривая без истории:10706
  Кривая без истории:10707
  Кривая без истории:10708
  Кривая без истории:10709
  Кривая без истории:10710
  Кривая без истории:10711
  Кривая без истории:10712
  Кривая без истории:10713
  Кривая без истории:10714
  Кривая без истории:10715
  Кривая без истории:10716
  Кривая без истории:10717
  Кривая без истории:10718
  Кривая без истории:10719
  Кривая без истории:10720
  Кривая без истории:10721
  Кривая без истории:10722
  Кривая без истории:10723
  Кривая без истории:10724
  Кривая без истории:10725
  Кривая без истории:10726
  Кривая без истории:10727
  Кривая без истории:10728
  Кривая без истории:10729
  Кривая без истории:10730
  Кривая без истории:10731
  Кривая без истории:10732
  Кривая без истории:10733
  Кривая без истории:10734
  Кривая без истории:10735
  Кривая без истории:10736
  Кривая без истории:10737
  Кривая без истории:10738
  Кривая без истории:10739
  Кривая без истории:10740
  Кривая без истории:10741
  Кривая без истории:10742
  Кривая без истории:10743
  Кривая без истории:10744
  Кривая без истории:10745
  Кривая без истории:10746
  Кривая без истории:10747
  Кривая без истории:10748
  Кривая без истории:10749
  Кривая без истории:10750
  Кривая без истории:10751
  Кривая без истории:10752
  Кривая без истории:10753
  Кривая без истории:10754
  Кривая без истории:10755
  Кривая без истории:10756
  Кривая без истории:10757
  Кривая без истории:10758
  Кривая без истории:10759
  Кривая без истории:10760
  Кривая без истории:10761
